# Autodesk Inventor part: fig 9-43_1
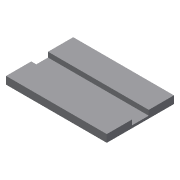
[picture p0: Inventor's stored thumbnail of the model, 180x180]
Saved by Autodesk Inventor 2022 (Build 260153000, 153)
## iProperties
Created: 2013-03
Part Number: fig 9-43_1
Material: Generic
Document SubType Name: Modeling
Designer: CADCIM
Density: 1 g/cm^3
Appearance: Default
Author: CADCIM
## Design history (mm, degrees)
sketch "Sketch1"
  geometry: L1 (-12.966, 10)-(17.034, 10); L2 (17.034, 10)-(17.034, -10); L3 (17.034, -10)-(-12.966, -10); L4 (-12.966, -10)-(-12.966, 10); 1 further point
  constraints: 8 end point, 2 parallel, 1 horizontal, 1 perpendicular
  dimensions: "d0" = 30 distance of L1.start L1.end; "d2" = 20 distance of L1.end L2.end
extrude "Extrusion1" new body sketch "Sketch1" distance "d3" = 2.25; taper "d4" = 0 deg
sketch "Sketch2"
  geometry: L1 (-12.966, 10)-(-12.966, -10) reference; L2 (-12.966, 2.498)-(87.034, 2.498); L3 (87.034, 2.498)-(87.034, -2.502); L4 (87.034, -2.502)-(-12.966, -2.502); L5 (-12.966, -2.502)-(-12.966, 2.498); 1 further point
  constraints: 8 end point, 2 parallel, 1 horizontal, 1 perpendicular, 1 point on line
  dimensions: "d5" = 5 distance of L2.end L3.end; "d7" = 100 distance of L2.start L2.end
extrude "Extrusion2" cut sketch "Sketch2" distance "d8" = 1.5; taper "d9" = 0 deg
body "Solid1"
